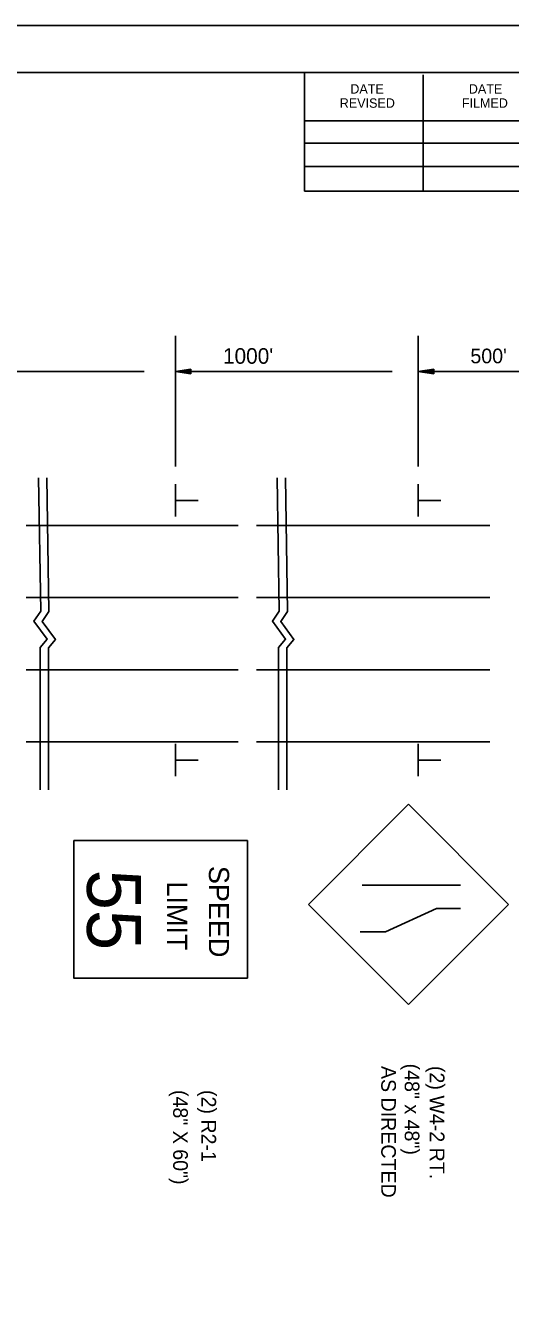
# Model space of a CAD drawing. Extents: x 1397271 to 1411271, y 376395 to 377888.
# Drawn here: x 1403500 to 1403782, y 377141 to 377888 of the extents above; entities that cross this region are included whole.
import ezdxf

# ---------------------------------------------------------------- set-up
doc = ezdxf.new("R2010")
doc.units = 0
for name, color, linetype in [('Default', 7, 'Continuous'), ('R_Border', 7, 'Continuous'), ('R_MOT', 7, 'Continuous'), ('R_No Plot', 7, 'Continuous')]:
    doc.layers.add(name, color=color, linetype=linetype)

msp = doc.modelspace()

# ---------------------------------------------------------------- linework, layer by layer
at = {"layer": 'Default'}
for p, q in [((1403586.76, 377707.31), (1403586.76, 377631.08)), ((1403728.23, 377707.31), (1403728.23, 377631.08)), ((1403442.43, 377686.54), (1403568.62, 377686.54)), ((1403595.83, 377687.9), (1403586.76, 377686.54)), ((1403586.76, 377686.54), (1403712.94, 377686.54)), ((1403595.83, 377685.18), (1403586.76, 377686.54)), ((1403595.83, 377687.67), (1403588.27, 377686.54)), ((1403595.83, 377685.41), (1403588.27, 377686.54)), ((1403595.83, 377687.44), (1403589.83, 377686.54)), ((1403595.83, 377685.64), (1403589.83, 377686.54)), ((1403595.83, 377687.22), (1403591.34, 377686.54)), ((1403595.83, 377685.86), (1403591.34, 377686.54)), ((1403595.83, 377686.98), (1403592.88, 377686.54)), ((1403595.83, 377686.1), (1403592.88, 377686.54)), ((1403595.83, 377686.75), (1403594.39, 377686.54)), ((1403595.83, 377686.33), (1403594.39, 377686.54)), ((1403595.83, 377685.18), (1403595.83, 377687.9)), ((1403737.3, 377687.9), (1403728.23, 377686.54)), ((1403728.23, 377686.54), (1403929.34, 377686.54)), ((1403737.3, 377685.18), (1403728.23, 377686.54)), ((1403737.3, 377687.67), (1403729.75, 377686.54)), ((1403737.3, 377685.41), (1403729.75, 377686.54)), ((1403737.3, 377687.44), (1403731.31, 377686.54)), ((1403737.3, 377685.64), (1403731.31, 377686.54)), ((1403737.3, 377687.22), (1403732.82, 377686.54)), ((1403737.3, 377685.86), (1403732.82, 377686.54)), ((1403737.3, 377686.98), (1403734.35, 377686.54)), ((1403737.3, 377686.1), (1403734.35, 377686.54)), ((1403737.3, 377686.75), (1403735.87, 377686.54)), ((1403737.3, 377686.33), (1403735.87, 377686.54)), ((1403737.3, 377685.18), (1403737.3, 377687.9)), ((1403499.87, 377596.8), (1403623.34, 377596.8)), ((1403634.04, 377596.8), (1403769.86, 377596.8)), ((1403499.87, 377554.76), (1403623.34, 377554.76)), ((1403634.04, 377554.76), (1403769.86, 377554.76)), ((1403499.87, 377512.73), (1403623.34, 377512.73)), ((1403634.04, 377512.73), (1403769.86, 377512.73)), ((1403499.87, 377470.69), (1403623.34, 377470.69)), ((1403634.04, 377470.69), (1403769.86, 377470.69))]:
    msp.add_line(p, q, dxfattribs=at)
at = {"layer": 'R_Border'}
for p, q in [((1402024.58, 377860.72), (1404237.88, 377860.72)), ((1403662.05, 377791.56), (1403662.05, 377860.72)), ((1403731.07, 377791.56), (1403731.07, 377859.32)), ((1403662.05, 377832.58), (1403936.17, 377832.58)), ((1403662.05, 377819.56), (1403936.17, 377819.56)), ((1403662.05, 377791.56), (1403662.05, 377805.98)), ((1403662.05, 377805.98), (1403936.17, 377805.98)), ((1404237.88, 377791.56), (1403662.05, 377791.56))]:
    msp.add_line(p, q, dxfattribs=at)
at = {"layer": 'R_MOT'}
for p, q in [((1403586.76, 377601.98), (1403586.76, 377620.9)), ((1403728.23, 377601.98), (1403728.23, 377620.9)), ((1403587.04, 377611.39), (1403599.95, 377611.39)), ((1403728.51, 377611.39), (1403741.42, 377611.39)), ((1403586.76, 377450.7), (1403586.76, 377469.62)), ((1403728.23, 377450.7), (1403728.23, 377469.62)), ((1403587.04, 377460.11), (1403599.95, 377460.11)), ((1403728.51, 377460.11), (1403741.42, 377460.11)), ((1403664.35, 377376.08), (1403722.61, 377434.34)), ((1403722.61, 377434.34), (1403780.87, 377376.08)), ((1403695.62, 377387.28), (1403752.93, 377387.28)), ((1403722.61, 377317.82), (1403664.35, 377376.08)), ((1403709.21, 377360.11), (1403738.82, 377373.7)), ((1403780.87, 377376.08), (1403722.61, 377317.82)), ((1403738.82, 377373.7), (1403752.93, 377373.7)), ((1403694.39, 377360.11), (1403709.21, 377360.11))]:
    msp.add_line(p, q, dxfattribs=at)
for points in [[(1403507.11, 377624.62), (1403508.29, 377546.87), (1403504.36, 377541.03), (1403512.01, 377530.56), (1403507.98, 377525.73), (1403507.97, 377442.87)], [(1403511.93, 377624.62), (1403513.12, 377546.67), (1403509.19, 377540.83), (1403516.84, 377530.36), (1403512.82, 377525.53), (1403512.8, 377442.87)], [(1403646.03, 377624.62), (1403647.22, 377546.87), (1403643.29, 377541.03), (1403650.94, 377530.56), (1403646.91, 377525.73), (1403646.9, 377442.87)], [(1403650.86, 377624.62), (1403652.05, 377546.67), (1403648.12, 377540.83), (1403655.77, 377530.36), (1403651.74, 377525.53), (1403651.73, 377442.87)]]:
    msp.add_lwpolyline(points, dxfattribs=at)
msp.add_lwpolyline([(1403628.74, 377333.01), (1403527.62, 377333.01), (1403527.62, 377413.24), (1403628.74, 377413.24)], close=True, dxfattribs=at)
at = {"layer": 'R_No Plot'}
msp.add_line((1401937.77, 377887.98), (1404271.14, 377887.98), dxfattribs=at)
for points in [[(1401937.72, 377887.98), (1404271.14, 377887.98), (1404271.14, 376394.59), (1401937.72, 376394.59)], [(1403662.05, 377860.72), (1403662.05, 377791.56), (1403912.17, 377791.56), (1403912.17, 377771.12), (1404074.57, 377771.12), (1404074.57, 377600.79), (1404237.88, 377600.79), (1404237.88, 376422.47), (1402024.58, 376422.47), (1402024.58, 377860.72)]]:
    msp.add_lwpolyline(points, close=True, dxfattribs=at)

# ---------------------------------------------------------------- texts
at = {"layer": 'Default'}
for s, height, p in [("1000'", 9.067, (1403614.47, 377691.01)), ("500'", 8.54, (1403758.59, 377691.28))]:
    msp.add_text(s, height=height, dxfattribs=at).set_placement(p)
at = {"layer": 'R_Border'}
for s, p in [('DATE', (1403688.65, 377848.4)), ('DATE', (1403757.67, 377848.4)), ('REVISED', (1403682.49, 377840.14)), ('FILMED', (1403753.61, 377840.14))]:
    msp.add_text(s, height=5.474, rotation=360, dxfattribs=at).set_placement(p)
at = {"layer": 'R_MOT'}
for s, height, p in [('SPEED', 11.763, (1403606.26, 377398.48)), ('55', 31.526, (1403535.29, 377396.29)), ('LIMIT', 11.763, (1403581.95, 377389.45)), ('AS DIRECTED ', 8.5402, (1403706.66, 377281.93)), ('(48" x 48")', 8.5402, (1403720.34, 377283.29)), ('(2) W4-2 RT.', 8.5402, (1403734.95, 377281.93)), ('(48" X 60")', 8.5402, (1403585.46, 377267.92)), ('(2) R2-1', 8.54, (1403601.95, 377267.92))]:
    msp.add_text(s, height=height, rotation=270, dxfattribs=at).set_placement(p)

doc.saveas('drawing.dxf')
